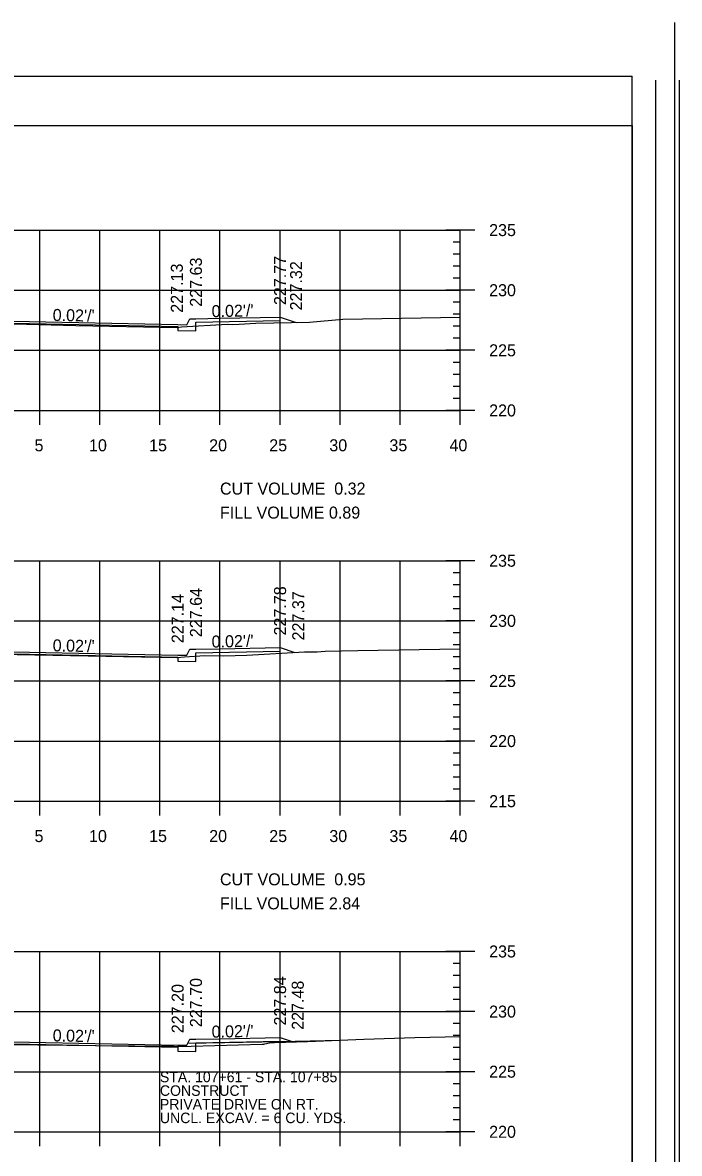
# Model space of a CAD drawing. Extents: x 1367903 to 1373764, y 376865 to 382130.
# Drawn here: x 1371751.5 to 1371860.9, y 377432.3 to 377620.4 of the extents above; entities that cross this region are included whole.
import ezdxf

# ---------------------------------------------------------------- set-up
doc = ezdxf.new("R2010")
doc.units = 0
for name, color, linetype in [('R_Axis', 7, 'Continuous'), ('R_Axis Annot', 7, 'Continuous'), ('R_Border', 7, 'Continuous'), ('R_Border PE', 7, 'Continuous'), ('R_Draft', 7, 'Continuous'), ('R_Drive', 7, 'Continuous'), ('R_Exist Surface', 7, 'Continuous'), ('R_Fin Surface', 7, 'Continuous'), ('R_Fin Surface Annot', 7, 'Continuous'), ('R_Grid', 7, 'Continuous')]:
    doc.layers.add(name, color=color, linetype=linetype)

msp = doc.modelspace()

# ---------------------------------------------------------------- linework, layer by layer
for points in [[(1371708.39, 377571.09), (1371708.39, 377570.42), (1371708.39, 377570.42), (1371708.39, 377569.06), (1371711.39, 377569.12), (1371711.39, 377569.78), (1371744.39, 377570.44), (1371777.39, 377569.78), (1371777.39, 377569.12), (1371780.39, 377569.06), (1371780.39, 377570.5), (1371794.39, 377570.78), (1371794.39, 377571.37)], [(1371708.39, 377516.12), (1371708.39, 377515.46), (1371708.39, 377515.46), (1371708.39, 377514.09), (1371711.39, 377514.15), (1371711.39, 377514.82), (1371744.39, 377515.48), (1371777.39, 377514.82), (1371777.39, 377514.15), (1371780.39, 377514.09), (1371780.39, 377515.54), (1371794.39, 377515.82), (1371794.39, 377516.4)], [(1371708.39, 377451.24), (1371708.39, 377450.57), (1371708.39, 377450.57), (1371708.39, 377449.21), (1371711.39, 377449.27), (1371711.39, 377449.94), (1371744.39, 377450.6), (1371777.39, 377449.94), (1371777.39, 377449.27), (1371780.39, 377449.21), (1371780.39, 377450.65), (1371794.39, 377450.93), (1371794.39, 377451.52)]]:
    msp.add_lwpolyline(points)
at = {"layer": 'R_Axis'}
for p, q in [((1371826.79, 377585.84), (1371821.99, 377585.84)), ((1371824.39, 377555.84), (1371824.39, 377585.84)), ((1371824.39, 377583.84), (1371823.19, 377583.84)), ((1371824.39, 377581.84), (1371823.19, 377581.84)), ((1371824.39, 377579.84), (1371823.19, 377579.84)), ((1371824.39, 377577.84), (1371823.19, 377577.84)), ((1371826.79, 377575.84), (1371821.99, 377575.84)), ((1371824.39, 377573.84), (1371823.19, 377573.84)), ((1371824.39, 377571.84), (1371823.19, 377571.84)), ((1371824.39, 377569.84), (1371823.19, 377569.84)), ((1371824.39, 377567.84), (1371823.19, 377567.84)), ((1371826.79, 377565.84), (1371821.99, 377565.84)), ((1371824.39, 377563.84), (1371823.19, 377563.84)), ((1371824.39, 377561.84), (1371823.19, 377561.84)), ((1371754.39, 377553.44), (1371754.39, 377558.24)), ((1371764.39, 377553.44), (1371764.39, 377558.24)), ((1371774.39, 377553.44), (1371774.39, 377558.24)), ((1371784.39, 377553.44), (1371784.39, 377558.24)), ((1371794.39, 377553.44), (1371794.39, 377558.24)), ((1371804.39, 377553.44), (1371804.39, 377558.24)), ((1371814.39, 377553.44), (1371814.39, 377558.24)), ((1371824.39, 377559.84), (1371823.19, 377559.84)), ((1371824.39, 377553.44), (1371824.39, 377558.24)), ((1371824.39, 377557.84), (1371823.19, 377557.84)), ((1371664.39, 377555.84), (1371824.39, 377555.84)), ((1371826.79, 377555.84), (1371821.99, 377555.84)), ((1371826.79, 377530.84), (1371821.99, 377530.84)), ((1371824.39, 377490.84), (1371824.39, 377530.84)), ((1371824.39, 377528.84), (1371823.19, 377528.84)), ((1371824.39, 377526.84), (1371823.19, 377526.84)), ((1371824.39, 377524.84), (1371823.19, 377524.84)), ((1371824.39, 377522.84), (1371823.19, 377522.84)), ((1371826.79, 377520.84), (1371821.99, 377520.84)), ((1371824.39, 377518.84), (1371823.19, 377518.84)), ((1371824.39, 377516.84), (1371823.19, 377516.84)), ((1371824.39, 377514.84), (1371823.19, 377514.84)), ((1371824.39, 377512.84), (1371823.19, 377512.84)), ((1371826.79, 377510.84), (1371821.99, 377510.84)), ((1371824.39, 377508.84), (1371823.19, 377508.84)), ((1371824.39, 377506.84), (1371823.19, 377506.84)), ((1371824.39, 377504.84), (1371823.19, 377504.84)), ((1371824.39, 377502.84), (1371823.19, 377502.84)), ((1371826.79, 377500.84), (1371821.99, 377500.84)), ((1371824.39, 377498.84), (1371823.19, 377498.84)), ((1371824.39, 377496.84), (1371823.19, 377496.84)), ((1371824.39, 377494.84), (1371823.19, 377494.84)), ((1371754.39, 377488.44), (1371754.39, 377493.24)), ((1371764.39, 377488.44), (1371764.39, 377493.24)), ((1371774.39, 377488.44), (1371774.39, 377493.24)), ((1371784.39, 377488.44), (1371784.39, 377493.24)), ((1371794.39, 377488.44), (1371794.39, 377493.24)), ((1371804.39, 377488.44), (1371804.39, 377493.24)), ((1371814.39, 377488.44), (1371814.39, 377493.24)), ((1371824.39, 377492.84), (1371823.19, 377492.84)), ((1371824.39, 377488.44), (1371824.39, 377493.24)), ((1371664.39, 377490.84), (1371824.39, 377490.84)), ((1371826.79, 377490.84), (1371821.99, 377490.84)), ((1371826.79, 377465.84), (1371821.99, 377465.84)), ((1371824.39, 377435.84), (1371824.39, 377465.84)), ((1371824.39, 377463.84), (1371823.19, 377463.84)), ((1371824.39, 377461.84), (1371823.19, 377461.84)), ((1371824.39, 377459.84), (1371823.19, 377459.84)), ((1371824.39, 377457.84), (1371823.19, 377457.84)), ((1371826.79, 377455.84), (1371821.99, 377455.84)), ((1371824.39, 377453.84), (1371823.19, 377453.84)), ((1371824.39, 377451.84), (1371823.19, 377451.84)), ((1371824.39, 377449.84), (1371823.19, 377449.84)), ((1371824.39, 377447.84), (1371823.19, 377447.84)), ((1371826.79, 377445.84), (1371821.99, 377445.84)), ((1371824.39, 377443.84), (1371823.19, 377443.84)), ((1371824.39, 377441.84), (1371823.19, 377441.84)), ((1371824.39, 377439.84), (1371823.19, 377439.84)), ((1371754.39, 377433.44), (1371754.39, 377438.24)), ((1371764.39, 377433.44), (1371764.39, 377438.24)), ((1371774.39, 377433.44), (1371774.39, 377438.24)), ((1371784.39, 377433.44), (1371784.39, 377438.24)), ((1371794.39, 377433.44), (1371794.39, 377438.24)), ((1371804.39, 377433.44), (1371804.39, 377438.24)), ((1371814.39, 377433.44), (1371814.39, 377438.24)), ((1371824.39, 377437.84), (1371823.19, 377437.84)), ((1371824.39, 377433.44), (1371824.39, 377438.24)), ((1371664.39, 377435.84), (1371824.39, 377435.84)), ((1371826.79, 377435.84), (1371821.99, 377435.84))]:
    msp.add_line(p, q, dxfattribs=at)
at = {"layer": 'R_Border'}
for p, q in [((1371860.06, 377620.35), (1371860.06, 377279.12)), ((1371648.7, 377611.47), (1371853.02, 377611.47)), ((1371853.02, 377280.59), (1371853.02, 377611.47)), ((1371853.02, 377446.03), (1371853.02, 377446.03))]:
    msp.add_line(p, q, dxfattribs=at)
at = {"layer": 'R_Border PE'}
for p, q in [((1371856.95, 377288.8), (1371856.95, 377610.76)), ((1371860.86, 377288.8), (1371860.86, 377610.76)), ((1371648.7, 377603.25), (1371853.02, 377603.25)), ((1371853.02, 377603.25), (1371853.02, 377288.8))]:
    msp.add_line(p, q, dxfattribs=at)
at = {"layer": 'R_Drive'}
for p, q in [((1371779.06, 377450.57), (1371794.39, 377450.88)), ((1371794.39, 377450.88), (1371804.39, 377451.09))]:
    msp.add_line(p, q, dxfattribs=at)
at = {"layer": 'R_Exist Surface'}
for points in [[(1371664.39, 377571.29), (1371666.48, 377571.25), (1371667.65, 377571.1), (1371683.84, 377570.22), (1371685.15, 377570.14), (1371700.55, 377569.93), (1371704.17, 377569.93), (1371710.77, 377569.93), (1371712.31, 377569.86), (1371722.81, 377570.05), (1371743.92, 377570.39), (1371760.4, 377569.97), (1371777.24, 377569.65), (1371777.97, 377569.72), (1371785.56, 377570.19), (1371786.47, 377570.16), (1371787.59, 377570.2), (1371790.38, 377570.36), (1371799.28, 377570.52), (1371804.82, 377571.01), (1371824.39, 377571.37)], [(1371664.39, 377516.51), (1371667.66, 377516.44), (1371672.43, 377515.85), (1371680.51, 377515.41), (1371687.47, 377515), (1371695.38, 377514.9), (1371711.85, 377514.88), (1371712.28, 377514.88), (1371712.38, 377514.88), (1371713.08, 377514.89), (1371744.01, 377515.4), (1371747.62, 377515.3), (1371777.2, 377514.76), (1371778.49, 377514.87), (1371781.89, 377515.08), (1371784.99, 377515), (1371788.85, 377515.13), (1371798.44, 377515.67), (1371800.57, 377515.71), (1371801.9, 377515.82), (1371807.33, 377515.93), (1371824.39, 377516.18)], [(1371744.27, 377450.41), (1371763.79, 377450.18), (1371776.73, 377450.09), (1371777.06, 377450.03), (1371779.6, 377450.1), (1371791.4, 377450.42), (1371791.63, 377450.42), (1371791.68, 377450.44), (1371791.88, 377450.49), (1371792.63, 377450.63), (1371793.46, 377450.71), (1371798.94, 377450.87), (1371808.33, 377451.26), (1371816.83, 377451.53), (1371824.39, 377451.7)]]:
    msp.add_lwpolyline(points, dxfattribs=at)
at = {"layer": 'R_Fin Surface'}
for points in [[(1371704.92, 377569.93), (1371708.39, 377571.09), (1371709.39, 377571.09), (1371709.89, 377570.09), (1371711.39, 377570.12), (1371733.39, 377570.56), (1371744.39, 377570.78), (1371755.39, 377570.56), (1371777.39, 377570.12), (1371778.89, 377570.09), (1371779.39, 377571.09), (1371780.39, 377571.09), (1371784.39, 377571.17), (1371794.39, 377571.37), (1371797.06, 377570.48)], [(1371704.68, 377514.89), (1371708.39, 377516.12), (1371709.39, 377516.12), (1371709.89, 377515.12), (1371711.39, 377515.15), (1371733.39, 377515.59), (1371744.39, 377515.81), (1371755.39, 377515.59), (1371777.39, 377515.15), (1371778.89, 377515.12), (1371779.39, 377516.12), (1371780.39, 377516.12), (1371784.39, 377516.2), (1371794.39, 377516.4), (1371796.86, 377515.58)], [(1371704.29, 377449.87), (1371708.39, 377451.24), (1371709.39, 377451.24), (1371709.89, 377450.24), (1371711.39, 377450.27), (1371733.39, 377450.71), (1371744.39, 377450.93), (1371755.39, 377450.71), (1371777.39, 377450.27), (1371778.89, 377450.24), (1371779.39, 377451.24), (1371780.39, 377451.24), (1371784.39, 377451.32), (1371794.39, 377451.52), (1371796.56, 377450.8)]]:
    msp.add_lwpolyline(points, dxfattribs=at)
at = {"layer": 'R_Grid'}
for p, q in [((1371664.39, 377585.84), (1371824.39, 377585.84)), ((1371754.39, 377555.84), (1371754.39, 377585.84)), ((1371764.39, 377555.84), (1371764.39, 377585.84)), ((1371774.39, 377555.84), (1371774.39, 377585.84)), ((1371784.39, 377555.84), (1371784.39, 377585.84)), ((1371794.39, 377555.84), (1371794.39, 377585.84)), ((1371804.39, 377555.84), (1371804.39, 377585.84)), ((1371814.39, 377555.84), (1371814.39, 377585.84)), ((1371824.39, 377555.84), (1371824.39, 377585.84)), ((1371664.39, 377575.84), (1371824.39, 377575.84)), ((1371664.39, 377565.84), (1371824.39, 377565.84)), ((1371664.39, 377555.84), (1371824.39, 377555.84)), ((1371664.39, 377530.84), (1371824.39, 377530.84)), ((1371754.39, 377490.84), (1371754.39, 377530.84)), ((1371764.39, 377490.84), (1371764.39, 377530.84)), ((1371774.39, 377490.84), (1371774.39, 377530.84)), ((1371784.39, 377490.84), (1371784.39, 377530.84)), ((1371794.39, 377490.84), (1371794.39, 377530.84)), ((1371804.39, 377490.84), (1371804.39, 377530.84)), ((1371814.39, 377490.84), (1371814.39, 377530.84)), ((1371824.39, 377490.84), (1371824.39, 377530.84)), ((1371664.39, 377520.84), (1371824.39, 377520.84)), ((1371664.39, 377510.84), (1371824.39, 377510.84)), ((1371664.39, 377500.84), (1371824.39, 377500.84)), ((1371664.39, 377490.84), (1371824.39, 377490.84)), ((1371664.39, 377465.84), (1371824.39, 377465.84)), ((1371754.39, 377435.84), (1371754.39, 377465.84)), ((1371764.39, 377435.84), (1371764.39, 377465.84)), ((1371774.39, 377435.84), (1371774.39, 377465.84)), ((1371784.39, 377435.84), (1371784.39, 377465.84)), ((1371794.39, 377435.84), (1371794.39, 377465.84)), ((1371804.39, 377435.84), (1371804.39, 377465.84)), ((1371814.39, 377435.84), (1371814.39, 377465.84)), ((1371824.39, 377435.84), (1371824.39, 377465.84)), ((1371664.39, 377455.84), (1371824.39, 377455.84)), ((1371664.39, 377445.84), (1371824.39, 377445.84)), ((1371664.39, 377435.84), (1371824.39, 377435.84))]:
    msp.add_line(p, q, dxfattribs=at)

# ---------------------------------------------------------------- texts
at = {"layer": 'R_Axis Annot'}
for s, p in [('235', (1371829.19, 377584.84)), ('230', (1371829.19, 377574.84)), ('225', (1371829.19, 377564.84)), ('220', (1371829.19, 377554.84)), ('5', (1371753.52, 377549.04)), ('10', (1371762.59, 377549.04)), ('15', (1371772.59, 377549.04)), ('20', (1371782.59, 377549.04)), ('25', (1371792.59, 377549.04)), ('30', (1371802.59, 377549.04)), ('35', (1371812.59, 377549.04)), ('40', (1371822.59, 377549.04)), ('CUT VOLUME  0.32', (1371784.39, 377541.84)), ('FILL VOLUME 0.89', (1371784.39, 377537.84)), ('235', (1371829.19, 377529.84)), ('230', (1371829.19, 377519.84)), ('225', (1371829.19, 377509.84)), ('220', (1371829.19, 377499.84)), ('215', (1371829.19, 377489.84)), ('5', (1371753.52, 377484.04)), ('10', (1371762.59, 377484.04)), ('15', (1371772.59, 377484.04)), ('20', (1371782.59, 377484.04)), ('25', (1371792.59, 377484.04)), ('30', (1371802.59, 377484.04)), ('35', (1371812.59, 377484.04)), ('40', (1371822.59, 377484.04)), ('CUT VOLUME  0.95', (1371784.39, 377476.84)), ('FILL VOLUME 2.84', (1371784.39, 377472.84)), ('235', (1371829.19, 377464.84)), ('230', (1371829.19, 377454.84)), ('225', (1371829.19, 377444.84)), ('220', (1371829.19, 377434.84))]:
    msp.add_text(s, height=2, dxfattribs=at).set_placement(p)
at = {"layer": 'R_Draft'}
for s, p in [('STA. 107+61 - STA. 107+85', (1371774.39, 377444.09)), ('CONSTRUCT', (1371774.39, 377441.82)), ('PRIVATE DRIVE ON RT.', (1371774.39, 377439.55)), ('UNCL. EXCAV. = 6 CU. YDS.', (1371774.39, 377437.28))]:
    msp.add_text(s, height=1.75, dxfattribs=at).set_placement(p)
at = {"layer": 'R_Fin Surface Annot'}
for s, rotation, p in [('227.63', 90, (1371781.39, 377573.09)), ('227.77', 90, (1371795.39, 377573.37)), ('227.13', 90, (1371778.21, 377572.09)), ('227.32', 90, (1371798.06, 377572.48)), ("0.02'/'", 1.1458, (1371783.02, 377571.34)), ("0.02'/'", 358.8542, (1371756.53, 377570.73)), ('227.64', 90, (1371781.39, 377518.12)), ('227.78', 90, (1371795.39, 377518.4)), ('227.14', 90, (1371778.34, 377517.12)), ('227.37', 90, (1371798.42, 377517.58)), ("0.02'/'", 1.1458, (1371783.02, 377516.38)), ("0.02'/'", 358.8542, (1371756.53, 377515.77)), ('227.20', 90, (1371778.34, 377452.24)), ('227.70', 90, (1371781.39, 377453.24)), ('227.84', 90, (1371795.39, 377453.52)), ('227.48', 90, (1371798.34, 377452.8)), ("0.02'/'", 358.8542, (1371756.53, 377450.89)), ("0.02'/'", 1.1458, (1371783.02, 377451.49))]:
    msp.add_text(s, height=2, rotation=rotation, dxfattribs=at).set_placement(p)

doc.saveas('drawing.dxf')
